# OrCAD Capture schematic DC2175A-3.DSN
size Custom; title: 9V - 36VIN TO 12V, 13A ACTIVE CLAMP; rev: 3; note: DEMO CIRCUIT 2175A
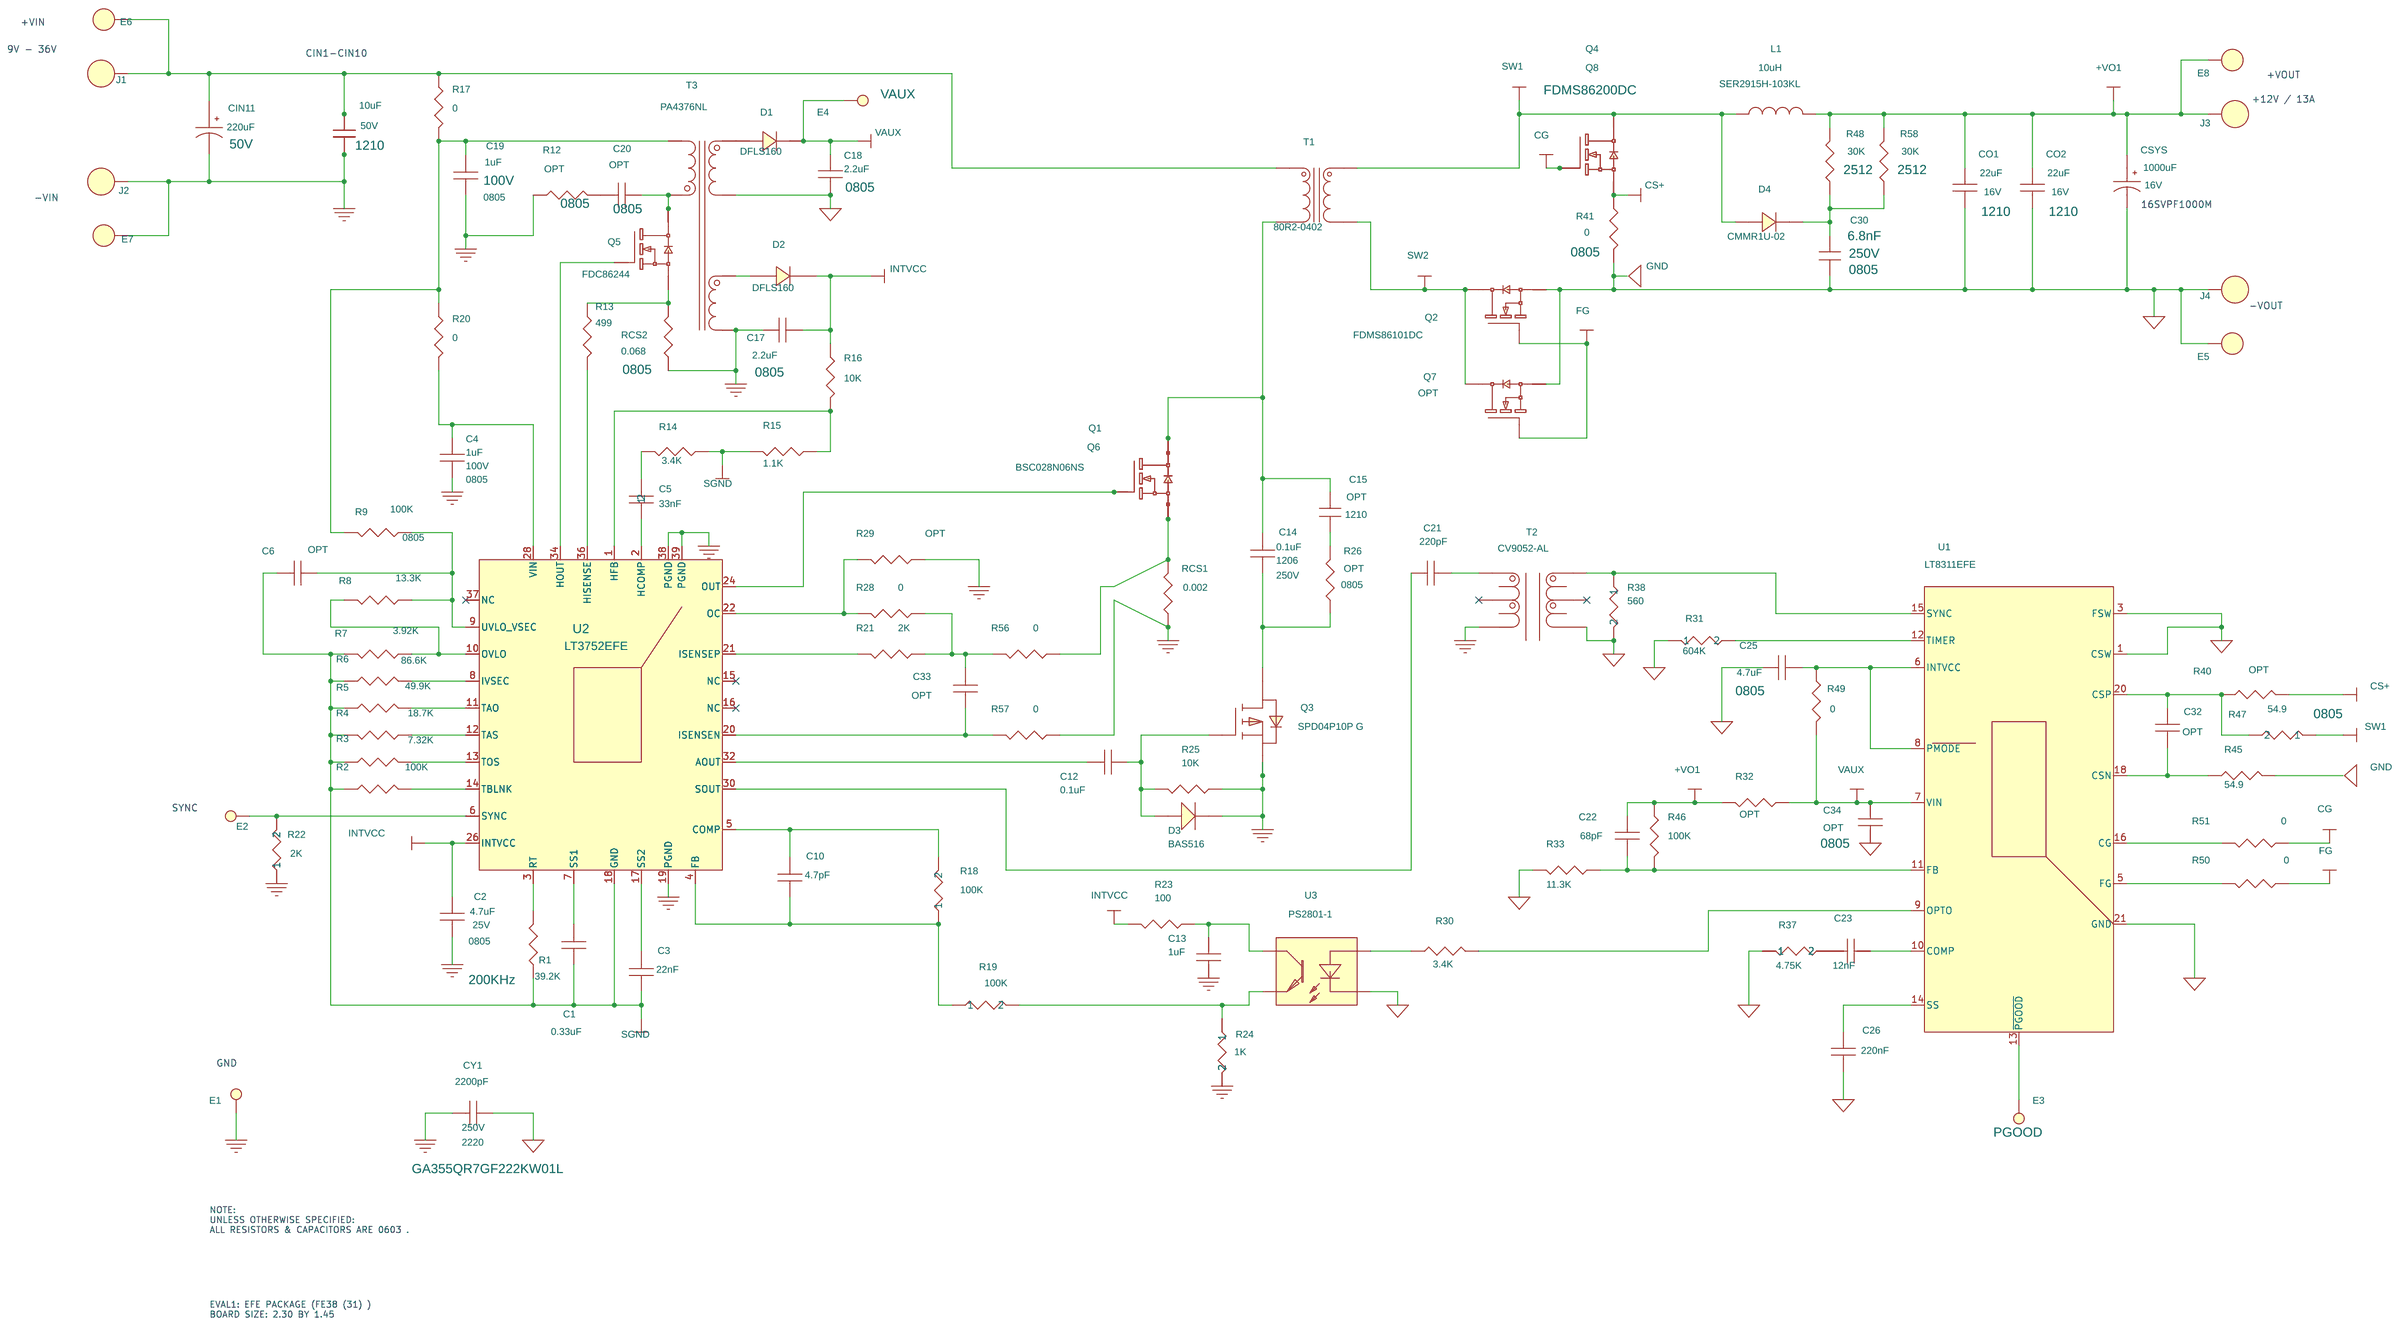
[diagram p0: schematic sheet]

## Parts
C1  0.33uF  [0603]
C2  4.7uF  [0805]
C3  22nF  [0603]
C4  1uF  [0805]
C5  33nF  [0603]
C6  OPT  [0603]
C10  4.7pF  [0603]
C12  0.1uF  [0603]
C13  1uF  [0603]
C14  0.1uF  [1206]
C15  OPT  [1210]
C17  2.2uF  [0805]
C18  2.2uF  [0805]
C19  1uF  [0805]
C20  OPT  [0805]
C21  220pF  [0603]
C22  68pF  [0603]
C23  12nF  [0603]
C25  4.7uF  [0805]
C26  220nF  [0603]
C30  6.8nF  [0805-1206]
C32  OPT  [0603]
C33  OPT  [0603]
C34  OPT  [0805]
CIN1  10uF  [1210]
CIN2  10uF  [1210]
CIN3  10uF  [1210]
CIN4  10uF  [1210]
CIN5  10uF  [1210]
CIN6  10uF  [1210]
CIN7  10uF  [1210]
CIN8  10uF  [1210]
CIN9  10uF  [1210]
CIN10  10uF  [1210]
CIN11  220uF  [CAP-CE-12.5X13.5]
CO1  22uF  [1210]
CO2  22uF  [1210]
CSYS  1000uF  [SANYO\12X10]
CY1  2200pF  [2220]
D1  DFLS160  [POWER-DI-123]
D2  DFLS160  [POWER-DI-123]
D3  BAS516  [SOD523]
D4  CMMR1U-02  [SOD-123]
E1  MillMax-2308(SM)  [MM/2308]
E2  MillMax-2308(SM)  [MM/2308]
E3  MillMax-2308(SM)  [MM/2308]
E4  MillMax-2308(SM)  [MM/2308]
E5  Testpoint  [MM/2501]
E6  Testpoint  [MM/2501]
E7  Testpoint  [MM/2501]
E8  Testpoint  [MM/2501]
J1  BANANA-JACK  [KEY-575-4]
J2  BANANA-JACK  [KEY-575-4]
J3  BANANA-JACK  [KEY-575-4]
J4  BANANA-JACK  [KEY-575-4]
L1  10uH  [IND-SER2900]
Q1  BSC028N06NS  [LFPAK]
Q2  FDMS86101DC  [LFPAK]
Q3  SPD04P10P G  [DPAK]
Q4  FDMS86200  [LFPAK]
Q5  FDC86244  [SUPERSOT-6]
Q6  BSC028N06NS  [LFPAK]
Q7  OPT  [LFPAK]
Q8  FDMS86200DC  [LFPAK]
R1  39.2K  [0603]
R2  100K  [0603]
R3  7.32K  [0603]
R4  18.7K  [0603]
R5  49.9K  [0603]
R6  86.6K  [0603]
R7  3.92K  [0603]
R8  13.3K  [0603]
R9  100K  [0805]
R12  OPT  [0805]
R13  499  [0603]
R14  3.4K  [0603]
R15  1.1K  [0603]
R16  10K  [0603]
R17  0  [0603]
R18  100K  [0603]
R19  100K  [0603]
R20  0  [0603]
R21  2K  [0603]
R22  2K  [0603]
R23  100  [0603]
R24  1K  [0603]
R25  10K  [0603]
R26  OPT  [0805]
R28  0  [0603]
R29  OPT  [0603]
R30  3.4K  [0603]
R31  604K  [0603]
R32  OPT  [0603]
R33  11.3K  [0603]
R37  4.75K  [0603]
R38  560  [0603]
R40  OPT  [0603]
R41  0  [0815]
R45  54.9  [0603]
R46  100K  [0603]
R47  54.9  [0805]
R48  30K  [2512]
R49  0  [0603]
R50  0  [0603]
R51  0  [0603]
R56  0  [0603]
R57  0  [0603]
R58  30K  [2512]
RCS1  0.002  [RES-KRL6432]
RCS2  0.068  [0805]
T1  80R2-0402  [TRANS-80R2-0402]
T2  CV9052-AL  [TRAN-PA3493NL]
T3  PA4376NL  [TRANS-PA0648]
U1  LT8311EFE  [FE-20L-CB(16)]
U2  Synch. Buck Reg.  [TSSOP-38(31)]
U3  Optocoupler  [PHOTOCOUPLER/NEC/PS2801-1]

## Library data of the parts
C1 = TMK212BJ104KG: 1st Part Field: 10V; 3rd Part Field: 1206
C2 = TMK212BJ104KG: 1st Part Field: 25V; 3rd Part Field: 1206; COMPFIXED: 1206
C3 C25 = TMK212BJ104KG: 1st Part Field: 25V
C4 = EMK212BJ105MG: 1st Part Field: 100V; 3rd Part Field: 1206
C5 = 08055C332KAT1A: 1ST PART FIELD: 25V
C6 = 08053C104KAT2A
C10 C33 = TMK212BJ104KG: 1st Part Field: 6.3V
C12 = TMK212BJ104KG: 1st Part Field: 6.3V; 3rd Part Field: 1206
C13 C26 = TMK212BJ104KG: 1st Part Field: 16V; 3rd Part Field: X5R
C14 = TMK212BJ104KG: 1st Part Field: 250V; COMPGROUP: 200V
C15 = CAP1210: 1ST PART FIELD: 200V; 6TH PART FIELD: 0.33uF
C17 C18 = EMK212BJ105MG: 1st Part Field: 10V
C19 = 08053C104KAT2A_2: 1ST PART FIELD: 100V; Voltage: 100V
C20 = 12063A222KAT2A_3: 1st Part Field: X7R
C21 = 08053C104KAT2A_1
C22 = 12063A222KAT2A_4: 1st Part Field: X7R
C23 = 12063A222KAT2A_1: 1st Part Field: X7R
C30 = CAP1206: 1ST PART FIELD: 250V; 6TH PART FIELD: 0805
C32 = 12063A222KAT2A_2: 1st Part Field: X7R
C34 = 12063A222KAT2A: 1st Part Field: X7R
CIN1-CIN10 = thcr70e2a475zt: 1%: X7R; 1st Part Field: 50V; 3RD PART FIELD: X7R; 4th Part Field: TDK
CIN11 = CAP_POL: 1st Part Field: 50V; 2nd Part Field: EMVH500_RA221MKE0S; VOLTAGE: ?V
CO1 CO2 = LMK325BJ106MN-T: 1st Part Field: 16V; 4th Part Field: TDK
CSYS = CAP_POL: VOLTAGE: 16V
CY1 = 12062A471KAT2A: 1st Part Field: 250V; 4th Part Field: murata; 5th Part Field: GA355QR7GF222KW01L
D1 D2 = DFLS160
D3 = DIODE_0
D4 = PDZ-B_0
E1 E2 = MillMax-2308(SM)
E3 = MillMax-2308(SM): 1ST PART FIELD: PGOOD
E4 = MillMax-2308(SM): 1ST PART FIELD: VAUX
E5-E8 = MillMax-2501_0
J1-J4 = BANANA-JACK
L1 = 33525_Schott_Corp_3.: 4th Part Field: SER2915H-103KL
Q1 = 2N7002_8
Q2 Q7 = 2N7002_6: 4TH PART FIELD: RENESAS
Q3 = Si2335DS_2: 4th Part Field: INFINEON
Q4 = 2N7002_6: 4TH PART FIELD: FAIRCHILD
Q5 = 2N7002_5: 4th Part Field: FAIRCHILD
Q6 = 2N7002_7
Q8 = 2N7002_6: 4TH PART FIELD: FAIRCHILD; 5TH PART FIELD: FDMS86200
R1 = CR10-334JM: 1%: 1%; 6TH PART FIELD: 200KHz
R2 R7 = CR10-4872FM
R3 R12-R17 R20 = CR10-8061FM
R4 R5 R8 R9 R21 R23 R25 R28 R29 R56 R57 = CR10-334JM: 1%: 1%
R6 = CR10-823JM
R18 = CR10-103JM_6
R19 = CR10-103JM_1
R22 = CR10-103JM_7
R24 = CR10-103JM_5
R26 = AAC-0805: 2ND PART FIELD: 1206; 4TH PART FIELD: VISHAY,; 6TH PART FIELD: 47
R30 = CR10-821JM
R31 = CR10-103JM
R32 R33 R40 R45 R46 R49 = CR10-1242FM
R37 = CR10-103JM_3
R38 = CR10-103JM_2
R41 = CR10-1242FM: 6TH PART FIELD: 0805
R47 = CR10-103JM_4
R48 R58 = AAC-1206: 4TH PART FIELD: VISHAY,
R50 R51 = AAC-0805: 2ND PART FIELD: 0805; 4TH PART FIELD: VISHAY,
RCS1 = LR2010-01-R005-F: 1ST PART FIELD: KRL6432E-M-R002-G; 4TH PART FIELD: 1225; 7TH PART FIELD: RES.,
RCS2 = LR2010-01-R005-F
T1 = TRANS-80R2-0402
T2 = coilcraft-q4470-b_1: 4th Part Field: PULSE ENG.
T3 = TRANSFORMER_FLAT_COMPACT_7
U1 = LT8311EFE_3
U2 = LTC1735CGN_18: 5th Part Field: LT3752EFE
U3 = HCPL-M453_3: 5th Part Field: PS2801-1

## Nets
SGND: C1.1 C3.1 C6.2 R1.1 R2.1 R3.1 R4.1 R5.1 R6.2 R7.2 R14.1 R15.2 U2.18(GND)
+VO1: C22.1 CO1.1 CO2.1 CSYS.1 E8.1 J3.1 L1.2 R32.1 R46.2 R48.2 R58.2
CG: Q4.4 Q8.4 R51.1
CS+: Q4.1 Q4.2 Q4.3 Q8.1 Q8.2 Q8.3 R40.1 R41.2
CS-: C18.2 C25.1 C26.2 C30.1 C34.2 CO1.2 CO2.2 CSYS.2 CY1.1 E5.1 J4.1 Q2.1 Q2.2 Q2.3 Q7.1 Q7.2 Q7.3 R31.1 R33.1 R37.1 R38.2 R41.1 R45.1 T2.4 T3.5 U1.1(CSW) U1.3(FSW) U1.21(GND) U3.2
FG: Q2.4 Q7.4 R50.1
INTVCC: C2.1 C17.2 D2.1(CATHODE) R16.1 R23.2 U2.26(INTVCC)
PRIGND: C2.2 C4.2 C13.2 C17.1 C19.1 CIN1.2 CIN2.2 CIN3.2 CIN4.2 CIN5.2 CIN6.2 CIN7.2 CIN8.2 CIN9.2 CIN10.2 CIN11.2 CY1.2 D3.1 E1.1 E7.1 J2.1 Q3.3(S) R12.1 R22.1 R24.2 R25.1 R29.1 R57.1 RCS1.1 RCS2.1 T2.3 T3.7 U2.19(PGND) U2.38(PGND) U2.39(PGND)
SW1: D4.2(ANODE) L1.1 Q4.5 Q8.5 R47.1 T1.1
SW2: Q2.5 Q7.5 T1.5
VAUX: C18.1 C34.1 D1.1(CATHODE) E4.1 R32.2 R49.1 U1.7(VIN)
N503684: CIN1.1 CIN2.1 CIN3.1 CIN4.1 CIN5.1 CIN6.1 CIN7.1 CIN8.1 CIN9.1 CIN10.1 CIN11.1 E6.1 J1.1 R17.1 T1.6
N16793008: E2.1 R22.2 U2.6(SYNC)
N16793076: C3.2 U2.17(SS2)
N16793181: C4.1 R20.2 U2.28(VIN)
N16793296: R7.1 R8.2 U2.10(OVLO)
N16793316: R15.1 R16.2 U2.1(HFB)
N16793461: Q5.3 U2.34(HOUT)
N16793494: D2.2(ANODE) T3.2
N16793586: R13.2 U2.36(HISENSE)
N16793608: R6.1 U2.8(IVSEC)
N16793618: C19.2 R9.2 R17.2 R20.1 T3.8
N16793713: R5.2 U2.11(TAO)
N16793719: R4.2 U2.12(TAS)
N16793723: Q5.4 R13.1 RCS2.2
N16793727: R3.2 U2.13(TOS)
N16793781: R2.2 U2.14(TBLNK)
N16793785: C1.2 U2.7(SS1)
N16794543: C12.1 D3.2 Q3.1(G) R25.2
N16841240: R19.2 R24.1 U3.3
N16847214: R1.2 U2.3(RT)
N16864383: C14.1 Q3.4(D) R26.1
N16890657: C14.2 C15.2 Q1.5 Q6.5 T1.10
N16897281: C15.1 R26.2
N16912996: Q1.1 Q1.2 Q1.3 Q6.1 Q6.2 Q6.3 R56.1 RCS1.2
N16935430: C12.2 U2.32(AOUT)
N16957737: C21.1 U2.30(SOUT)
N17040755: C13.1 R23.1 U3.4
N17088199: C10.2 R18.2 U2.5(COMP)
N17147226: R38.1 T2.6 U1.15(SYNC)
N17262282: C5.2 R14.2
N17283185: Q1.4 Q6.4 U2.24(OUT)
N17328438: C5.1 U2.2(HCOMP)
N17348911: C10.1 R18.1 R19.1 U2.4(FB)
N17460716: R28.2 R29.2 U2.22(OC)
N17479781: R21.2 U2.21(ISENSEP)
N17499352: C6.1 R8.1 R9.1 U2.9(UVLO_VSEC)
N17580592: C33.2 R21.1 R28.1 R56.2
N18688418: C20.1 Q5.1 Q5.2 Q5.5 Q5.6 T3.1
N19065647: C21.2 T2.1
N19275704: R30.1 U3.1
N19276965: R30.2 U1.9(OPTO)
N19284388: R31.2 U1.12(TIMER)
N19318511: C22.2 R33.2 R46.1 U1.11(FB)
N19327779: C23.1 U1.10(COMP)
N19337679: C26.1 U1.14(SS)
N19343467: E3.1 U1.13(~{PGOOD})
N19355736: C32.1 R40.2 R47.2 U1.20(CSP)
N19383797: C32.2 R45.2 U1.18(CSN)
N19432300: R51.2 U1.16(CG)
N19432753: R50.2 U1.5(FG)
N19502047: C30.2 D4.1(CATHODE) R48.1 R58.1
N19720449: C25.2 R49.2 U1.6(INTVCC) U1.8(PMODE)
N20101157: C33.1 R57.2 U2.20(ISENSEN)
N20121731: C20.2 R12.2
N20121736: D1.2(ANODE) T3.4
N20123814: C23.2 R37.2

Not connected (* = marked no-connect by the designer): T2 2* 5*; U2 15(NC)* 16(NC)* 37(NC)*

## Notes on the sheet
- +VIN
- 9V - 36V
- CIN1-CIN10
- +VOUT
- +12V / 13A
- -VIN
- 16SVPF1000M
- -VOUT
- SYNC
- GND
- NOTE:
  UNLESS OTHERWISE SPECIFIED:
  ALL RESISTORS & CAPACITORS ARE 0603 .
- EVAL1: EFE PACKAGE (FE38 (31) )
  BOARD SIZE: 2.30 BY 1.45
